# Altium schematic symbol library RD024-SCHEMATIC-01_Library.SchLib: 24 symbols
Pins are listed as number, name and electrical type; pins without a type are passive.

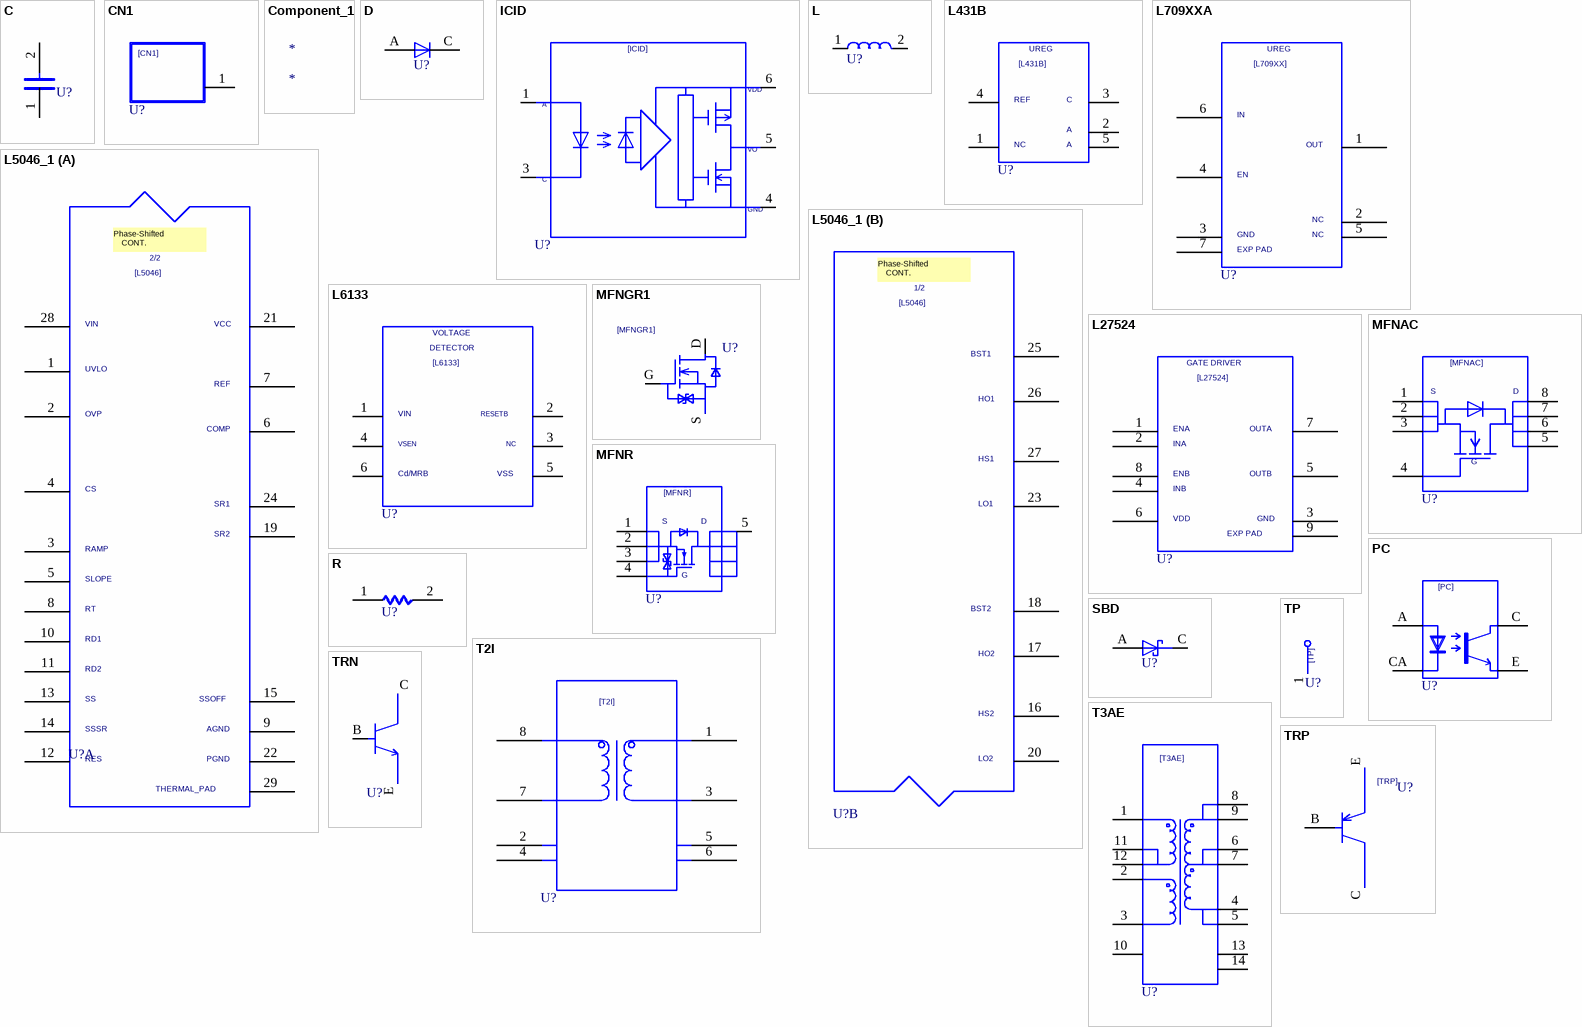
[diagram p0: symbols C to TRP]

## C
designator U?  (value not drawn)
OriginalSymbolOrigin: (2540,7620)
pins: 1, 2

## CN1
designator U?  (value not drawn)
OriginalSymbolOrigin: (2540,12700)
pins: 1

## Component_1
designator *

## D
designator U?  (value not drawn)
SAVEAREA0: -225,-91,12804,7836; SAVECOUNT: 3; TIME: 14:49:55; UPDATEUSER: 19870035; UPDATETIME: 14:20:16; OriginalSymbolOrigin: (5080,5080)
pins: A, C

## ICID
designator U?  (value not drawn)
TIME: 11:37:10; UPDATEUSER: cae; UPDATETIME: 10:02:13; SAVECOUNT: 16; SAVEAREA0: -15781,-397,59072,38480; OriginalSymbolOrigin: (2540,35560)
pins: 1, 3, 4, 5, 6

## L
designator U?  (value not drawn)
OriginalSymbolOrigin: (2540,5080)
pins: 1, 2

## L431B
designator U?  (value not drawn)
SAVEAREA0: -12224,-318,37706,25614; TIME: 11:47:14; UPDATEUSER: cae; UPDATETIME: 15:43:57; SAVECOUNT: 6; OriginalSymbolOrigin: (5080,22860)
pins: 1, 2, 3, 4, 5

## L709XXA
designator U?  (value not drawn)
SAVECOUNT: 38; SAVEAREA0: -24553,-450,60279,43610; TIME: 14:46:30; UPDATEUSER: cae; UPDATETIME: 12:49:59; OriginalSymbolOrigin: (7620,40640)
pins: 1, 2, 3, 4, 5, 6, 7

## L5046_1
designator U?  (value not drawn)
SAVEAREA0: -71804,-1007,117827,97484; TIME: 14:38:41; UPDATEUSER: cae; UPDATETIME: 09:49:47; SAVECOUNT: 16; OriginalSymbolOrigin: (7620,93980)
part A pins: 1, 2, 3, 4, 5, 6, 7, 8, 9, 10, 11, 12, 13, 14, 15, 19, 21, 22, 24, 28, 29
part B pins: 16, 17, 18, 20, 23, 25, 26, 27

## L6133
designator U?  (value not drawn)
TIME: 13:21:52; UPDATEUSER: cae; UPDATETIME: 10:15:35; SAVECOUNT: 15; SAVEAREA0: -9663,-435,45411,35893; OriginalSymbolOrigin: (5080,33020)
pins: 1, 2, 3, 4, 5, 6

## L27524
designator U?  (value not drawn)
SAVEAREA0: -18325,-397,56528,38480; SAVECOUNT: 17; TIME: 12:23:18; UPDATEUSER: cae; UPDATETIME: 15:16:57; OriginalSymbolOrigin: (7620,35560)
pins: 1, 2, 3, 4, 5, 6, 7, 8, 9

## MFNAC
designator U?  (value not drawn)
TIME: 18:29:30; UPDATEUSER: 19990028; UPDATETIME: 14:45:16; SAVECOUNT: 26; SAVEAREA0: -10143,-336,37609,28718; OriginalSymbolOrigin: (5080,25400)
pins: 1, 2, 3, 4, 5, 6, 7, 8

## MFNGR1
designator U?  (value not drawn)
SAVECOUNT: 24; SAVEAREA0: -14204,-8572,26849,21288; TIME: 16:49:03; UPDATEUSER: ikeda-k; UPDATETIME: 18:49:38; OriginalSymbolOrigin: (2540,10160)
pins: D, G, S

## MFNR
designator U?  (value not drawn)
SAVEAREA0: -11373,-4619,33654,28142; TIME: 18:57:44; UPDATEUSER: ikeda-k; UPDATETIME: 16:18:19; SAVECOUNT: 11; OriginalSymbolOrigin: (5080,20320)
pins: 1, 2, 3, 4, 5

## PC
designator U?  (value not drawn)
OriginalSymbolOrigin: (5080,17780)
pins: A, C, CA, E

## R
designator U?  (value not drawn)
OriginalSymbolOrigin: (5080,5080)
pins: 1, 2

## SBD
designator U?  (value not drawn)
SAVEAREA0: -4630,-153,17114,13055; TIME: 14:49:55; UPDATEUSER: fukuda-y; UPDATETIME: 08:16:22; SAVECOUNT: 9; OriginalSymbolOrigin: (5080,5080)
pins: A, C

## T2I
designator U?  (value not drawn)
SAVEAREA0: -21366,-459,62077,41078; SAVECOUNT: 8; TIME: 14:27:07; UPDATEUSER: 19990028; UPDATETIME: 13:00:08; OriginalSymbolOrigin: (7620,38100)
pins: 1, 2, 3, 4, 5, 6, 7, 8

## T3AE
designator U?  (value not drawn)
SAVEAREA0: -34674,-485,56770,47009; TIME: 17:49:49; UPDATEUSER: cae; UPDATETIME: 15:15:30; SAVECOUNT: 3; OriginalSymbolOrigin: (5080,43180)
pins: 1, 2, 3, 4, 5, 6, 7, 8, 9, 10, 11, 12, 13, 14

## TP
designator U?  (value not drawn)
TIME: 16:12:21; UPDATEUSER: fukuda-y; UPDATETIME: 16:18:11; SAVECOUNT: 2; SAVEAREA0: -242,-92,12810,7836; OriginalSymbolOrigin: (0,7620)
pins: 1

## TRN
designator U?  (value not drawn)
TIME: 09:39:04; UPDATEUSER: 19910145; UPDATETIME: 15:12:10; SAVECOUNT: 8; SAVEAREA0: -6194,-158,18648,15662; OriginalSymbolOrigin: (2540,17780)
pins: B, C, E

## TRP
designator U?  (value not drawn)
TIME: 09:39:04; UPDATEUSER: 19870035; UPDATETIME: 15:34:42; SAVECOUNT: 12; SAVEAREA0: -5466,-244,29263,20886; OriginalSymbolOrigin: (5080,22860)
pins: B, C, E

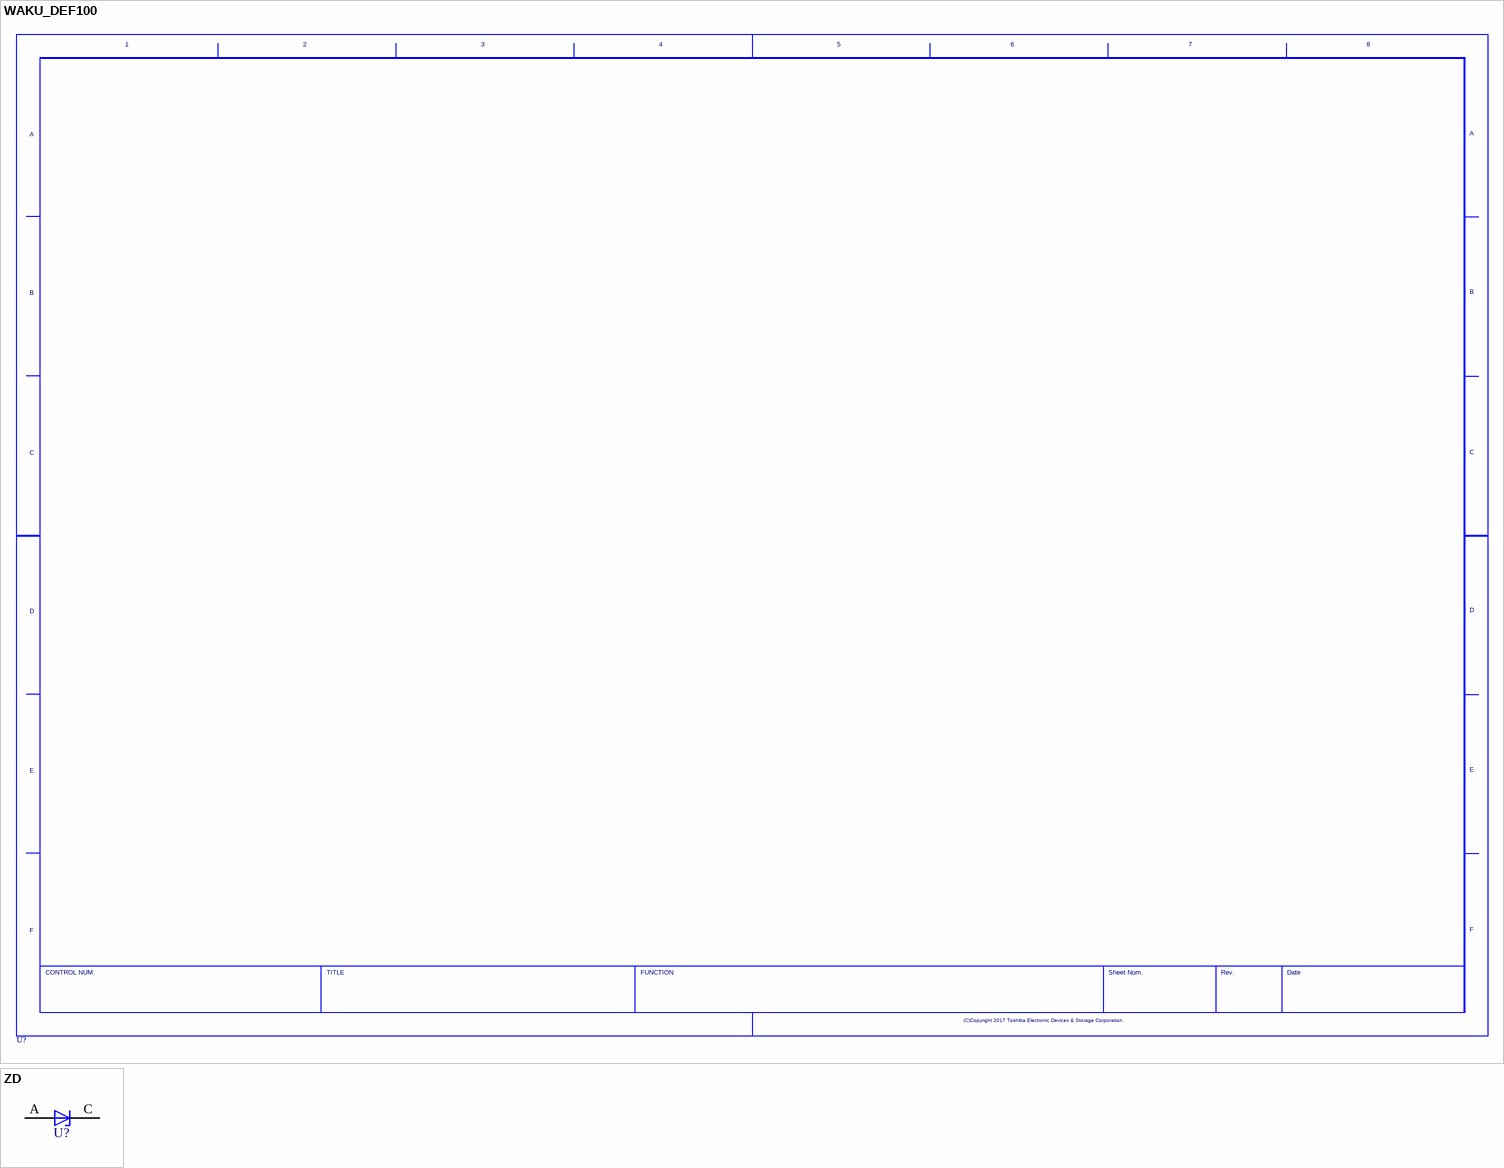
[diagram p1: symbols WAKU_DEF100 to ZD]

## WAKU_DEF100
designator U?  (value not drawn)
PLOTTIME: HH:MM; SAVEAREA0: -63393,-16950,474261,314592; TIME: 14:30:25; UPDATEUSER: cae; UPDATETIME: 18:29:18; SAVECOUNT: 3; OriginalSymbolOrigin: (10160,284480)

## ZD
designator U?  (value not drawn)
SAVEAREA0: -4630,-153,17114,13055; TIME: 14:49:55; UPDATEUSER: fukuda-y; UPDATETIME: 08:18:42; SAVECOUNT: 6; OriginalSymbolOrigin: (5080,5080)
pins: A, C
